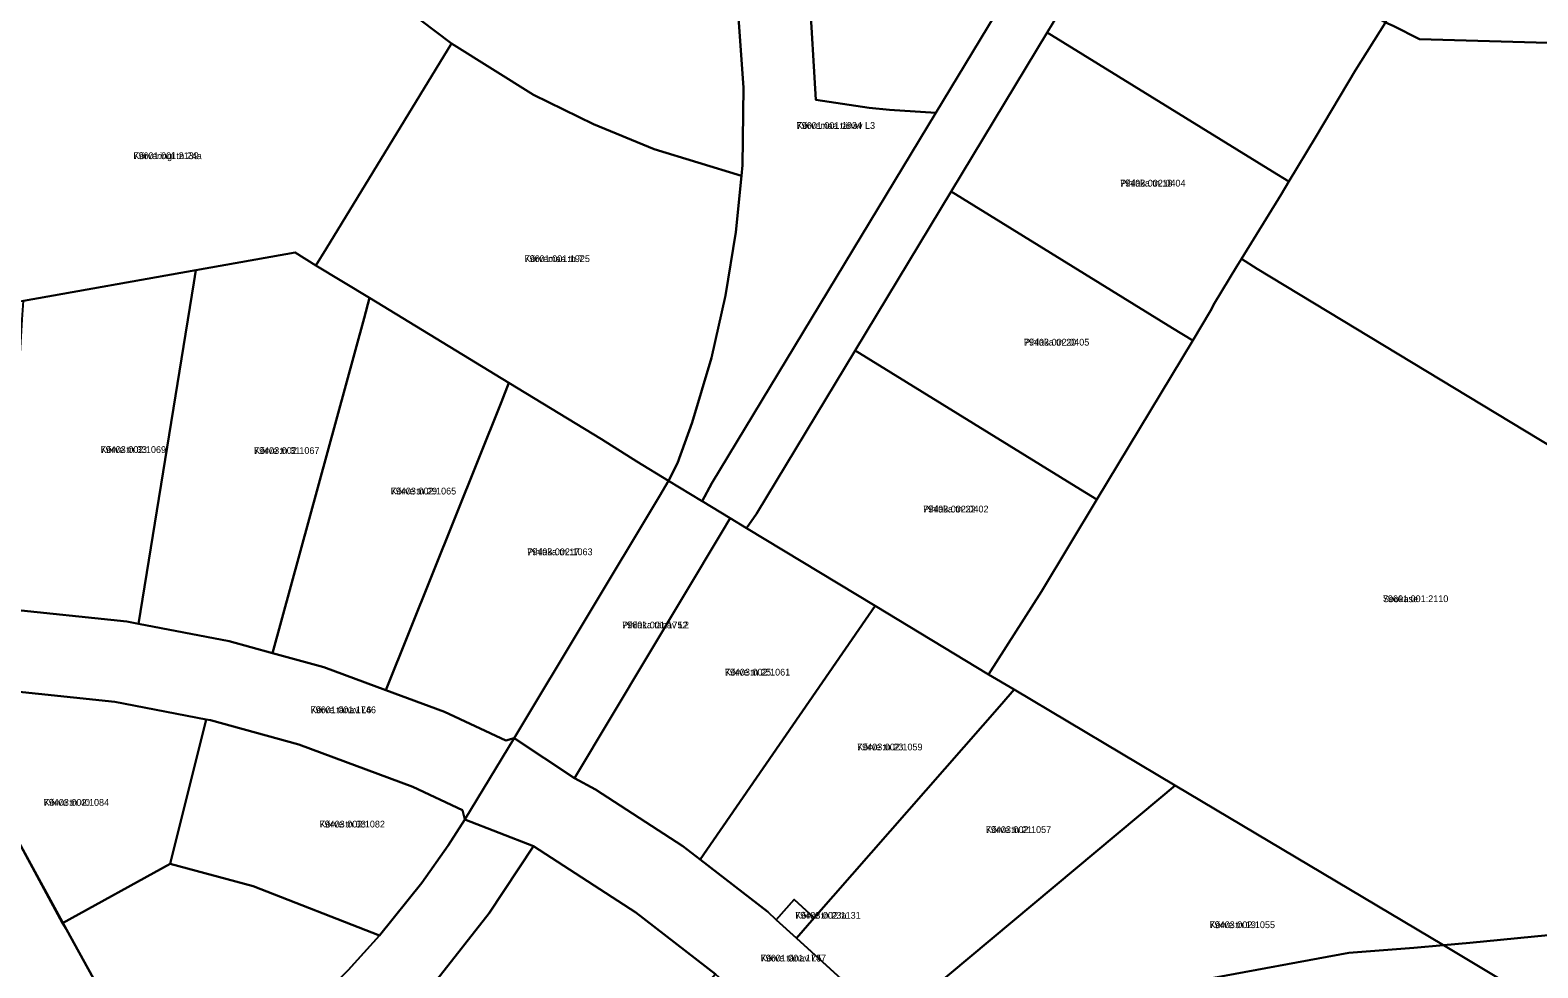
# Model space of a CAD drawing. Extents: x 625111 to 706696, y 6474150 to 6504223.
# Drawn here: x 660539.3 to 660873.5, y 6478878.1 to 6479086.1 of the extents above; entities that cross this region are included whole.
import ezdxf

# ---------------------------------------------------------------- set-up
doc = ezdxf.new("R2010")
doc.units = 0
for name, color, linetype in [('L_AADRESS', 7, 'Continuous'), ('PIIR', 7, 'Continuous'), ('TUNNUS', 7, 'Continuous')]:
    doc.layers.add(name, color=color, linetype=linetype)

msp = doc.modelspace()

# ---------------------------------------------------------------- linework, layer by layer
at = {"layer": 'PIIR'}
for points in [[(660993.91, 6479186.61), (660994.85, 6479185.64), (661029.57, 6479168.54), (661031.46, 6479167.32), (660983.43, 6479080.18), (660981.11, 6479080.24), (660968.59, 6479080.6), (660855.02, 6479083.83), (660847.26, 6479084.05), (660841.46, 6479087.02), (660839.69, 6479087.72), (660855.69, 6479119.04), (660874.2, 6479149.25), (660892.48, 6479178.86), (660914.91, 6479212.84), (660923.12, 6479225.28), (660925.49, 6479223.81), (660988.39, 6479184.61), (660991.34, 6479182.76)], [(660632.66, 6479083.11), (660615.79, 6479095.94), (660646.7, 6479106.15), (660654.26, 6479109.34), (660668.77, 6479116.94), (660679.44, 6479123.55), (660683.01, 6479124.84), (660686.81, 6479124.33), (660690.13, 6479121.87), (660691.65, 6479118.71), (660692.26, 6479115.98), (660695.96, 6479094.06), (660697.39, 6479073.34), (660697.18, 6479056.13), (660696.94, 6479053.75), (660677.63, 6479059.69), (660664.16, 6479065.18), (660650.89, 6479071.73)], [(660786.1, 6479120.78), (660835.66, 6479090.18), (660839.69, 6479087.72), (660833.08, 6479077.16), (660824.28, 6479062.37), (660818.31, 6479052.46), (660814.65, 6479054.71), (660764.75, 6479085.52)], [(660712.04, 6479094.22), (660724.73, 6479114.56), (660756.37, 6479094.79), (660740.04, 6479067.7), (660729.77, 6479068.37), (660725.26, 6479068.86), (660713.41, 6479070.61)], [(660587.93, 6479091.22), (660615.79, 6479095.94), (660632.66, 6479083.11), (660604.86, 6479037.55), (660602.63, 6479033.89), (660597.99, 6479036.72), (660576.02, 6479032.81), (660537.81, 6479026.02), (660501.39, 6479018.95), (660500.54, 6479023.32), (660513.34, 6479087.8), (660564.2, 6479090.22)], [(660841.46, 6479087.02), (660847.26, 6479084.05), (660855.02, 6479083.83), (660968.59, 6479080.6), (660968.62, 6479056.62), (660962.28, 6479056.74), (660954.44, 6479044.88), (660960.92, 6479031.52), (660936.37, 6478992.12), (660920.63, 6478966.93), (660811.3, 6479033.15), (660807.8, 6479035.31), (660816.59, 6479049.58), (660818.31, 6479052.46), (660824.28, 6479062.37), (660833.08, 6479077.16), (660839.69, 6479087.72)], [(660800.95, 6479023.79), (660796.98, 6479017.21), (660792.5, 6479019.97), (660743.45, 6479050.26), (660764.75, 6479085.52), (660814.65, 6479054.71), (660818.31, 6479052.46), (660816.59, 6479049.58), (660807.8, 6479035.31), (660806.71, 6479033.55), (660801.8, 6479025.5)], [(660604.86, 6479037.55), (660632.66, 6479083.11), (660650.89, 6479071.73), (660664.16, 6479065.18), (660677.63, 6479059.69), (660696.94, 6479053.75), (660695.7, 6479041.24), (660693.45, 6479027.18), (660690.29, 6479013.36), (660686, 6478999.02), (660682.78, 6478990.05), (660680.77, 6478986.12), (660673.77, 6478990.39), (660665.9, 6478995.32), (660645.42, 6479007.81), (660614.5, 6479026.66), (660602.63, 6479033.89)], [(660743.45, 6479050.26), (660792.5, 6479019.97), (660796.98, 6479017.21), (660775.71, 6478981.93), (660771.13, 6478984.76), (660722.15, 6479015)], [(660593.01, 6478947.9), (660583.37, 6478950.55), (660563.3, 6478954.42), (660575.56, 6479030), (660576.02, 6479032.81), (660597.99, 6479036.72), (660602.63, 6479033.89), (660614.5, 6479026.66), (660613.29, 6479022.21)], [(660920.63, 6478966.93), (660875.82, 6478885.33), (660858.41, 6478883.66), (660852.55, 6478883.09), (660793.1, 6478918.52), (660757.41, 6478939.79), (660751.74, 6478943.17), (660763.43, 6478961.57), (660775.71, 6478981.93), (660796.98, 6479017.21), (660800.95, 6479023.79), (660801.8, 6479025.5), (660806.71, 6479033.55), (660807.8, 6479035.31), (660811.3, 6479033.15)], [(660563.3, 6478954.42), (660560.67, 6478954.93), (660533.75, 6478957.7), (660537.5, 6479021.85), (660537.81, 6479026.02), (660576.02, 6479032.81), (660575.56, 6479030)], [(660618.13, 6478939.66), (660604.37, 6478944.77), (660593.01, 6478947.9), (660613.29, 6479022.21), (660614.5, 6479026.66), (660645.42, 6479007.81), (660643.77, 6479003.59)], [(660698.1, 6478975.6), (660700.26, 6478978.77), (660722.15, 6479015), (660771.13, 6478984.76), (660775.71, 6478981.93), (660763.43, 6478961.57), (660751.74, 6478943.17), (660726.61, 6478958.36)], [(660678.75, 6478982.67), (660646.54, 6478929.03), (660644.7, 6478928.5), (660631.1, 6478934.84), (660618.13, 6478939.66), (660643.77, 6479003.59), (660645.42, 6479007.81), (660665.9, 6478995.32), (660673.77, 6478990.39), (660680.77, 6478986.12)], [(660659.91, 6478920.18), (660646.54, 6478929.03), (660678.75, 6478982.67), (660680.77, 6478986.12), (660688.06, 6478981.67), (660688.23, 6478981.57), (660694.47, 6478977.8), (660692.64, 6478974.74)], [(660687.77, 6478902.11), (660683.96, 6478905.05), (660664.57, 6478917.63), (660659.91, 6478920.18), (660692.64, 6478974.74), (660694.47, 6478977.8), (660698.1, 6478975.6), (660726.61, 6478958.36), (660724.44, 6478955.26)], [(660986.89, 6478959.98), (661086.27, 6478955.62), (661056.26, 6478926.11), (661034.15, 6478904.56), (660999.96, 6478870.7), (660954.3, 6478826.09), (660952.37, 6478822.91), (660928.87, 6478837.12), (660898.29, 6478855.61), (660872.92, 6478870.95), (660852.55, 6478883.09), (660858.41, 6478883.66), (660875.82, 6478885.33), (660920.63, 6478966.93), (660928, 6478962.52), (660980.45, 6478960.29)], [(660503.03, 6478957.62), (660510.19, 6478958.12), (660532.91, 6478957.79), (660533.75, 6478957.7), (660560.67, 6478954.93), (660563.3, 6478954.42), (660583.37, 6478950.55), (660593.01, 6478947.9), (660604.37, 6478944.77), (660618.13, 6478939.66), (660631.1, 6478934.84), (660644.7, 6478928.5), (660646.54, 6478929.03), (660635.65, 6478911.02), (660635.11, 6478913.06), (660624.12, 6478918.23), (660598.84, 6478927.62), (660579.27, 6478933.01), (660578.28, 6478933.2), (660558.04, 6478937.11), (660531.86, 6478939.8), (660510.68, 6478940.11)], [(660713.07, 6478889.22), (660708.63, 6478893.27), (660704.68, 6478888.76), (660702.78, 6478890.49), (660687.77, 6478902.11), (660724.44, 6478955.26), (660726.61, 6478958.36), (660751.74, 6478943.17), (660757.41, 6478939.79), (660754.69, 6478936.68)], [(660578.28, 6478933.2), (660570.33, 6478901.13), (660546.46, 6478887.97), (660536.74, 6478905.94), (660530.58, 6478906.58), (660511.1, 6478906.84), (660510.68, 6478940.11), (660531.86, 6478939.8), (660558.04, 6478937.11)], [(660729.13, 6478864.99), (660719.91, 6478874.87), (660709.12, 6478884.71), (660713.07, 6478889.22), (660754.69, 6478936.68), (660757.41, 6478939.79), (660793.11, 6478918.51), (660789.46, 6478915.48)], [(660635.65, 6478911.02), (660631.95, 6478905.22), (660626.09, 6478896.92), (660616.74, 6478885.24), (660588.69, 6478896.19), (660570.33, 6478901.13), (660578.28, 6478933.2), (660579.27, 6478933.01), (660598.84, 6478927.62), (660624.12, 6478918.23), (660635.11, 6478913.06)], [(660635.65, 6478911.02), (660646.54, 6478929.03), (660659.91, 6478920.18), (660664.57, 6478917.63), (660683.96, 6478905.05), (660687.77, 6478902.11), (660702.78, 6478890.49), (660704.68, 6478888.76), (660709.12, 6478884.71), (660719.91, 6478874.87), (660729.13, 6478864.99), (660738.19, 6478855.29), (660749.67, 6478840.55), (660729.96, 6478829.97), (660723.37, 6478840.14), (660724.01, 6478843.9), (660707.25, 6478862.06), (660691.19, 6478876.7), (660673.54, 6478890.35), (660650.87, 6478905.05)], [(660738.19, 6478855.29), (660729.13, 6478864.99), (660789.46, 6478915.48), (660793.11, 6478918.51), (660852.55, 6478883.09), (660846.01, 6478882.56), (660831.58, 6478881.39), (660799.58, 6478875.48), (660774.73, 6478868.15), (660743.59, 6478855.35)], [(660635.65, 6478911.02), (660650.87, 6478905.05), (660640.99, 6478890.19), (660629.39, 6478875.45), (660621.06, 6478866.23), (660616.74, 6478861.84), (660607.01, 6478852.76), (660594.43, 6478842.49), (660577.85, 6478831.04), (660570.15, 6478845.09), (660583.71, 6478854.44), (660593.84, 6478862.52), (660601.76, 6478869.65), (660609.79, 6478877.6), (660616.74, 6478885.24), (660626.09, 6478896.92), (660631.95, 6478905.22)], [(660536.74, 6478905.94), (660547.35, 6478886.6), (660570.15, 6478845.09), (660555.66, 6478838.59), (660542.36, 6478834.27), (660527.13, 6478831.77), (660505.76, 6478831.73), (660488.23, 6478835.27), (660472.65, 6478841.22), (660449.57, 6478855.99), (660436.45, 6478862.55), (660460, 6478899.66), (660469.06, 6478901.95), (660511.1, 6478906.84), (660530.58, 6478906.58)], [(660650.87, 6478905.05), (660673.54, 6478890.35), (660691.19, 6478876.7), (660650.9, 6478830), (660621.06, 6478866.23), (660629.39, 6478875.45), (660640.99, 6478890.19)], [(660546.46, 6478887.97), (660570.33, 6478901.13), (660588.69, 6478896.19), (660616.74, 6478885.24), (660609.79, 6478877.6), (660601.76, 6478869.65), (660593.84, 6478862.52), (660583.71, 6478854.44), (660570.15, 6478845.09), (660547.35, 6478886.6)], [(660704.68, 6478888.76), (660708.63, 6478893.27), (660713.07, 6478889.22), (660709.12, 6478884.71)], [(660776.16, 6478851.48), (660749.67, 6478840.55), (660738.19, 6478855.29), (660743.59, 6478855.35), (660774.73, 6478868.15), (660799.58, 6478875.48), (660831.58, 6478881.39), (660846.01, 6478882.56), (660852.55, 6478883.09), (660872.92, 6478870.95), (660867.8, 6478869.03), (660860.02, 6478867.65), (660833.75, 6478865.56), (660803.28, 6478859.96), (660790.29, 6478856.06), (660780.06, 6478852.99)]]:
    msp.add_lwpolyline(points, close=True, dxfattribs=at)
for points in [[(660786.1, 6479120.78), (660764.75, 6479085.52), (660743.45, 6479050.26), (660722.15, 6479015), (660700.26, 6478978.77), (660698.1, 6478975.6), (660694.47, 6478977.8), (660688.23, 6478981.57), (660690.42, 6478985.55), (660740.04, 6479067.7), (660756.37, 6479094.79)], [(660712.04, 6479094.22), (660713.41, 6479070.61), (660725.26, 6479068.86), (660729.77, 6479068.37), (660740.04, 6479067.7), (660690.42, 6478985.55), (660688.23, 6478981.57), (660688.06, 6478981.67), (660680.77, 6478986.12), (660682.78, 6478990.05), (660686, 6478999.02), (660690.29, 6479013.36), (660693.45, 6479027.18), (660695.7, 6479041.24), (660696.94, 6479053.75), (660697.18, 6479056.13), (660697.39, 6479073.34), (660695.96, 6479094.06)]]:
    msp.add_lwpolyline(points, dxfattribs=at)

# ---------------------------------------------------------------- texts
at = {"layer": 'L_AADRESS'}
for s, p in [('Kõrvemaa tänav L3', (660709.18, 6479064.16)), ('Kõrveringi tn 24a', (660562.16, 6479057.45)), ('Pihlaka tn 18', (660780.89, 6479051.37)), ('Kõrvemaa tn 7', (660648.86, 6479034.62)), ('Pihlaka tn 20', (660759.56, 6479016.1)), ('Kõrve tn 33', (660554.89, 6478992.29)), ('Kõrve tn 31', (660588.9, 6478992.07)), ('Kõrve tn 29', (660619.21, 6478983.08)), ('Pihlaka tn 22', (660737.22, 6478979.09)), ('Pihlaka tn 17', (660649.45, 6478969.61)), ('Sookase', (660839.15, 6478959.2)), ('Pihlaka tänav L2', (660670.5, 6478953.39)), ('Kõrve tn 25', (660693.26, 6478942.92)), ('Kõrve tänav L6', (660601.43, 6478934.57)), ('Kõrve tn 23', (660722.59, 6478926.33)), ('Kõrve tn 40', (660542.27, 6478914.04)), ('Kõrve tn 38', (660603.42, 6478909.22)), ('Kõrve tn 21', (660751.11, 6478908)), ('Kõrve tn 23a', (660708.88, 6478888.99)), ('Kõrve tn 19', (660800.73, 6478886.9)), ('Kõrve tänav L5', (660701.2, 6478879.5))]:
    msp.add_text(s, height=1.5, dxfattribs=at).set_placement(p)
at = {"layer": 'TUNNUS'}
for s, p in [('79601:001:1934', (660709.18, 6479064.16)), ('79601:001:2139', (660562.16, 6479057.45)), ('79403:002:0404', (660780.89, 6479051.37)), ('79601:001:1925', (660648.86, 6479034.62)), ('79403:002:0405', (660759.56, 6479016.1)), ('79403:002:1069', (660554.89, 6478992.29)), ('79403:002:1067', (660588.9, 6478992.07)), ('79403:002:1065', (660619.21, 6478983.08)), ('79403:002:0402', (660737.22, 6478979.09)), ('79403:002:1063', (660649.45, 6478969.61)), ('79601:001:2110', (660839.15, 6478959.2)), ('79601:001:1752', (660670.5, 6478953.39)), ('79403:002:1061', (660693.26, 6478942.92)), ('79601:001:1746', (660601.43, 6478934.57)), ('79403:002:1059', (660722.59, 6478926.33)), ('79403:002:1084', (660542.27, 6478914.04)), ('79403:002:1082', (660603.42, 6478909.22)), ('79403:002:1057', (660751.11, 6478908)), ('79403:002:1131', (660708.88, 6478888.99)), ('79403:002:1055', (660800.73, 6478886.9)), ('79601:001:1747', (660701.2, 6478879.5))]:
    msp.add_text(s, height=1.5, dxfattribs=at).set_placement(p)

doc.saveas('drawing.dxf')
